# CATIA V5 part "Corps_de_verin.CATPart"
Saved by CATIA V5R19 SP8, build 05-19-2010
Part number: Corps de verin
Revision: ANY
Definition: UNKNOWN
Nomenclature: Corps de vérin
Source: Unknown
Bounding box of the stored display mesh (mm): x -7.5 to 7.5, y -7.49 to 7.49, z -12 to 190
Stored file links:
  D:\Documents\1_Travail\1 - ac-limoges.fr\OneDrive - ac-limoges.fr\STI2D_Turgot\2 -2I2D\3_SEQUENCE_Serre_Connectée\3- Spécificités\ITEC\EC 3 Ouverture automatique\Simulation  Ouverture Automatique\Corps_de_verin.CATPart
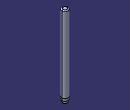
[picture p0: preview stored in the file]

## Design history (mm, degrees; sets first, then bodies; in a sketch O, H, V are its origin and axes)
Body1 "NONE" (main body)
  Solid1: solid without history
